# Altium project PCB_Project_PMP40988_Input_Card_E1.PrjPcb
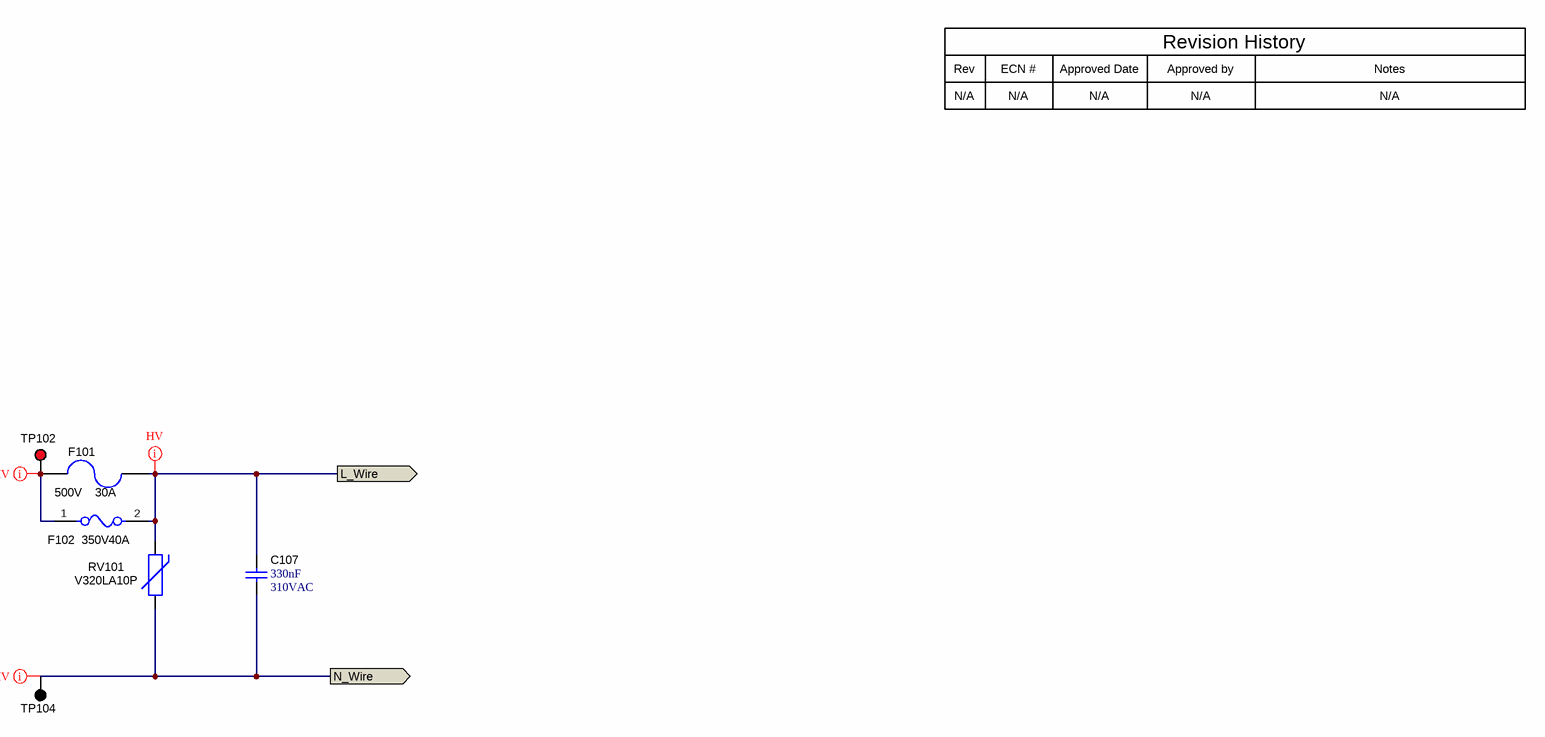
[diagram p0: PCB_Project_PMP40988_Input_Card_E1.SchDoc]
CopyrightYear: 2021; PCB_Layout: San Chen; PCB_Rev: E1; PRJ_Customer: Public Release; PRJ_Engineer: San Chen; PRJ_Number: PMP40988_Input Card; PRJ_Title: PMP40988 Input Card; SCH_Rev: E1; TechSupport: http://www.ti.com/support; TID: N/A
1 sheet, 6 parts. Net scope: flat (ports and power ports of the same name join across sheets).
Board file: PCB_Project_PMP40988_Input_Card_E1.PcbDoc

## Sheet PCB_Project_PMP40988_Input_Card_E1.SchDoc
size 431 x 279 mm; Date: Not shown in title block; ApprovedBy: Not shown in title block; CheckedBy: Not shown in title block; Author: Not shown in title block; CompanyName: Not shown in title block; DrawnBy: San Chen; Engineer: Not shown in title block; Organization: Not shown in title block; Address1: Not shown in title block; Address2: Not shown in title block; Address3: Not shown in title block; Address4: Not shown in title block; DocumentNumber: 1; Revision: Use project parameter SCH_Rev; SheetNumber: 1; SheetTotal: 3; PageSetup: Record=PageOptions¦CenterHorizontal=True¦CenterVertical=True¦PrintScale=1.00¦XCorrection=1.00¦YCorrection=1.00¦PrintKind=0¦BorderSize=5000000¦LeftOffset=0¦BottomOffset=0¦Orientation=2¦PaperLength=1000¦PaperWidth=1000¦Scale=100¦PaperSource=15¦PrintQuality=600¦MediaType=1¦DitherType=10¦PaperKind=Letter¦PrintScaleMode=1

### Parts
C107  330nF  Rated Voltage: 310VAC  [WCAP-FTXX_L18W8.5H14.5]
F101  Irating_A: 30A  VAC_V: 500V  [Fuse_505_MXE]  (hidden comment: 0ADEP9300-RE)
F102  Fuse Current: 40A  VDC_V: 350V  [FP-0684L9400-01_SMD2-MFG]  (hidden comment: 0684L9400-01)
RV101  V320LA10P  [VAR_LA_320V]
TP102  L  [Keystone5000]  (value not drawn)
TP104  N  [Keystone5001]  (value not drawn)

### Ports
L_Wire (out), N_Wire (out)

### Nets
L_Wire: C107.2 F101.2 F102.2 RV101.2 ; port L_Wire
N_Wire: C107.1 RV101.1 TP104.1 ; port N_Wire
NetF101_1: F101.1 F102.1 TP102.1

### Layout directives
net class HV: L_Wire, N_Wire, NetF101_1

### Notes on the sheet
- Rev
- N/A
- ECN #
- Approved Date
- Approved by
- Revision History
- Notes

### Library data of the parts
C107 = 890334025034: WCAP-FTXX Film Capacitor, THT, L18W8.5H14.5, 330nF, 310V; Manufacturer: Wurth Elektronik; Insulation Resistance: 30000MOhm; Dissipation Factor@100kHz: 2%; Capacitance Tolerance: +/-10%; Dissipation Factor@1kHz: 0.1%; Dissipation Factor@10kHz: 0.2%; Rate of Voltage Rise: 260V/us; Pitch: 15mm; Technical Reference: MX2P015334K275ASPB16000
F101 = CMP-0003520-2: Fuse, 30 A, 500VAC, TH; Manufacturer: Bel Fuse Inc.; SizeAreaWB_mm2: 376.1121; Interrupt_AC: 30kA; Interrupt_DC: 20kA; SizeZ_mm: 7.285; SizeX_mm: 39.86; SizeY_mm: 6.985; SizeArea_mm2: 278.4221; Rtyp_Ohm: 7.3m; MeltingTyp: 68
F102 = CMP-0092647-1: 40 A 350 V AC DC Fuse Board Mount (Cartridge Style Excluded) Holder Cartridge, Non-Standard; Manufacturer: Bel Fuse; Res_ohm: 0.0016Ω; AEC Qualified: Yes; Fuse Speed: Fast; SizeZ_mm: 4.85mm; Fuse I2T: 195A2Sec; AEC Grade: Grade 1
RV101 = CMP-0002098-2: Varistor, 420 V, TH; Manufacturer: Littelfuse; Value: 420 V
TP102 = 5000: Test Point, Miniature, Red, TH; Manufacturer: Keystone; CompType: Test Point Loop; U/M: EA
TP104 = 5001: Test Point, Miniature, Black, TH; Manufacturer: Keystone; CompType: Test Point Loop; U/M: EA

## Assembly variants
001: not fitted F102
